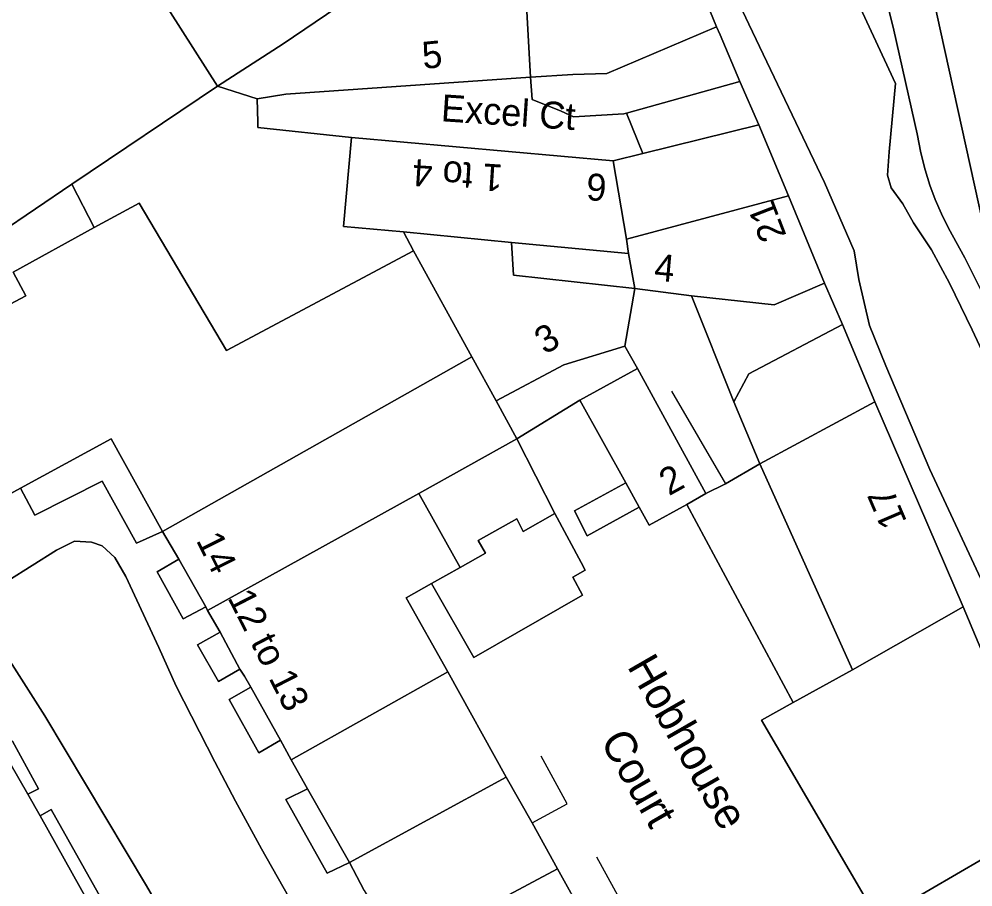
# Model space of a CAD drawing. Extents: x 529240 to 530363, y 179600 to 180767.
# Drawn here: x 529795.1 to 529848.2, y 180519 to 180567.3 of the extents above; entities that cross this region are included whole.
import ezdxf

# ---------------------------------------------------------------- set-up
doc = ezdxf.new("R2010")
doc.units = 0
for name, color, linetype in [('Building', 7, 'Continuous'), ('General surface', 7, 'Continuous'), ('Road Or Track', 7, 'Continuous'), ('Roadside', 7, 'Continuous'), ('Unclassified', 7, 'Continuous')]:
    doc.layers.add(name, color=color, linetype=linetype)

msp = doc.modelspace()

# ---------------------------------------------------------------- linework, layer by layer
at = {"layer": 'Building'}
for points in [[(529855.95, 180595.65), (529833.9, 180581.35), (529837.65, 180573.95), (529841.7, 180575.05), (529843.75, 180566.65), (529845.05, 180560.9), (529845.25, 180559.85), (529845.5, 180558.9), (529845.75, 180558.05), (529846.05, 180557.25), (529846.4, 180556.45), (529846.8, 180555.65), (529847.7, 180554), (529850.25, 180548.9)], [(529849.65, 180551.65), (529844.25, 180576.15), (529842, 180575.7), (529841.8, 180576.65), (529840.55, 180576.35), (529838.3, 180580.5), (529851.8, 180589.75)], [(529849.65, 180551.65), (529844.25, 180576.15), (529842, 180575.7), (529841.8, 180576.65), (529840.55, 180576.35), (529838.3, 180580.5), (529851.8, 180589.75), (529852.15, 180588.15), (529860.1, 180589.65)], [(529850.25, 180548.9), (529847.7, 180554), (529846.8, 180555.65), (529846.4, 180556.45), (529846.05, 180557.25), (529845.75, 180558.05), (529845.5, 180558.9), (529845.25, 180559.85), (529845.05, 180560.9), (529843.75, 180566.65), (529841.7, 180575.05), (529837.65, 180573.95), (529833.9, 180581.35)], [(529799.55, 180573.9), (529806.15, 180563.55)], [(529832.1, 180571.3), (529832.25, 180570.9), (529833.9, 180566.85)], [(529809.8, 180565.9), (529814, 180568.75)], [(529823.35, 180567.7), (529823.55, 180564.05)], [(529823.55, 180564.05), (529825.9, 180564.2), (529827.8, 180564.25), (529833.9, 180566.85)], [(529833.9, 180566.85), (529834.1, 180566.4), (529835.2, 180563.8)], [(529806.15, 180563.55), (529809.8, 180565.9)], [(529809.95, 180563.1), (529812.62, 180563.29), (529823.55, 180564.05)], [(529823.55, 180564.05), (529823.65, 180562.8), (529825.25, 180562.15), (529825.95, 180561.85), (529828.75, 180562), (529828.9, 180562.05)], [(529798.05, 180558.1), (529806.15, 180563.55)], [(529806.15, 180563.55), (529808.35, 180562.85)], [(529828.9, 180562.05), (529835.2, 180563.8)], [(529835.2, 180563.8), (529836.25, 180561.4)], [(529808.35, 180562.85), (529809.95, 180563.1)], [(529828.9, 180562.05), (529829.8, 180559.8)], [(529829.8, 180559.8), (529836.25, 180561.4)], [(529836.25, 180561.4), (529837.9, 180557.45)], [(529813.6, 180560.7), (529813.15, 180555.75), (529816.5, 180555.45)], [(529813.6, 180560.7), (529828.15, 180559.4)], [(529828.15, 180559.4), (529829.8, 180559.8)], [(529828.9, 180555.05), (529828.15, 180559.4)], [(529790.85, 180552.7), (529791, 180552.45), (529794.3, 180554.9), (529794, 180555.35), (529798.05, 180558.1)], [(529828.9, 180555.05), (529837.9, 180557.45)], [(529837.9, 180557.45), (529839.9, 180552.6)], [(529793, 180540), (529795.2, 180541.2), (529800.25, 180543.95), (529803.1, 180538.8), (529820.3, 180548.5), (529817.05, 180554.4), (529806.65, 180548.85), (529801.8, 180557.05), (529799.3, 180555.7), (529794.8, 180553.2), (529795.5, 180551.9), (529788.45, 180548.15)], [(529799.3, 180555.7), (529801.8, 180557.05), (529806.65, 180548.85), (529817.05, 180554.4)], [(529786.1, 180549.05), (529787.55, 180549.65), (529788.45, 180548.15), (529795.5, 180551.9), (529794.8, 180553.2), (529799.3, 180555.7)], [(529816.5, 180555.45), (529822.5, 180554.85)], [(529816.5, 180555.45), (529817.05, 180554.4)], [(529829, 180554.25), (529828.9, 180555.05)], [(529822.5, 180554.85), (529829, 180554.25)], [(529822.5, 180554.85), (529822.6, 180553.05), (529829.35, 180552.3)], [(529817.05, 180554.4), (529820.3, 180548.5)], [(529829.35, 180552.3), (529829, 180554.25)], [(529828.8, 180549.1), (529829.35, 180552.3)], [(529829.35, 180552.3), (529832.5, 180551.9)], [(529832.5, 180551.9), (529837.1, 180551.4), (529839.9, 180552.6)], [(529839.9, 180552.6), (529840.9, 180550.3)], [(529832.5, 180551.9), (529834.85, 180546)], [(529840.9, 180550.3), (529835.7, 180547.55), (529834.85, 180546)], [(529840.9, 180550.3), (529842.7, 180546)], [(529821.65, 180546.05), (529825.4, 180548.05), (529828.8, 180549.1)], [(529829.5, 180547.85), (529828.8, 180549.1)], [(529803.1, 180538.8), (529820.3, 180548.5)], [(529820.3, 180548.5), (529821.65, 180546.05)], [(529829.5, 180547.85), (529826.3, 180546.1)], [(529833.3, 180540.9), (529829.5, 180547.85)], [(529821.65, 180546.05), (529822.8, 180543.95)], [(529822.8, 180543.95), (529826.3, 180546.1)], [(529826.3, 180546.1), (529828.85, 180541.5)], [(529834.85, 180546), (529836.3, 180542.55)], [(529836.3, 180542.55), (529842.7, 180546)], [(529842.7, 180546), (529847.6, 180534.6)], [(529795.2, 180541.2), (529800.25, 180543.95), (529803.1, 180538.8)], [(529822.8, 180543.95), (529817.35, 180540.9)], [(529836.3, 180542.55), (529834.4, 180541.45)], [(529836.3, 180542.55), (529841.45, 180531.1)], [(529793, 180540), (529795.2, 180541.2)], [(529828.85, 180541.5), (529829.6, 180540.15)], [(529834.4, 180541.45), (529833.3, 180540.9)], [(529817.35, 180540.9), (529805.6, 180534.4)], [(529817.35, 180540.9), (529819.65, 180536.8)], [(529832.25, 180540.3), (529833.3, 180540.9)], [(529829.6, 180540.15), (529830.15, 180539.15), (529832.25, 180540.3)], [(529832.25, 180540.3), (529838.15, 180529.3)], [(529824.9, 180539.8), (529826.37, 180537.08), (529826.6, 180536.65), (529825.9, 180536.25), (529826.45, 180535.25), (529820.4, 180531.8), (529818.05, 180535.9)], [(529819.65, 180536.8), (529821.05, 180537.6), (529820.65, 180538.3), (529822.8, 180539.5), (529823.15, 180538.8), (529824.9, 180539.8)], [(529803.1, 180538.8), (529804, 180537.25)], [(529804, 180537.25), (529805.5, 180534.6)], [(529818.05, 180535.9), (529819.65, 180536.8)], [(529816.65, 180535.1), (529818.05, 180535.9)], [(529816.65, 180535.1), (529818.95, 180531)], [(529805.5, 180534.6), (529805.6, 180534.4)], [(529805.6, 180534.4), (529806.3, 180533.2)], [(529847.6, 180534.6), (529841.45, 180531.1)], [(529847.6, 180534.6), (529852.55, 180522.85), (529848.7, 180520.6)], [(529806.3, 180533.2), (529807.4, 180531.15)], [(529807.4, 180531.15), (529807.65, 180530.75), (529808, 180530.15)], [(529841.45, 180531.1), (529838.15, 180529.3)], [(529810.25, 180526.1), (529818.95, 180531)], [(529818.95, 180531), (529822.2, 180525.15)], [(529808, 180530.15), (529809.65, 180527.2)], [(529838.15, 180529.3), (529836.4, 180528.3), (529842.1, 180518.55)], [(529809.65, 180527.2), (529810.25, 180526.1)], [(529795.6, 180524.2), (529794.1, 180526.8)], [(529810.25, 180526.1), (529811.15, 180524.5)], [(529822.2, 180525.15), (529813.5, 180520.4)], [(529822.2, 180525.15), (529823.65, 180522.6)], [(529796.3, 180523), (529795.6, 180524.2)], [(529811.15, 180524.5), (529813.5, 180520.4)], [(529801.1, 180514.4), (529796.3, 180523)], [(529823.65, 180522.6), (529825.05, 180520.05)], [(529848.7, 180520.6), (529842.85, 180517.2)], [(529813.5, 180520.4), (529814.3, 180518.85)], [(529825.05, 180520.05), (529816.35, 180515.4)], [(529825.05, 180520.05), (529826.55, 180517.35)]]:
    msp.add_lwpolyline(points, dxfattribs=at)
for points in [[(529860.1, 180589.65), (529852.15, 180588.15), (529851.8, 180589.75), (529838.3, 180580.5), (529840.55, 180576.35), (529841.8, 180576.65), (529842, 180575.7), (529844.25, 180576.15), (529849.65, 180551.65), (529857.95, 180553.2), (529857.2, 180556.65), (529859.1, 180557.1), (529862.7, 180540.75), (529880.3, 180546.95), (529872.25, 180583.85), (529871.15, 180583.6), (529861.7, 180581.55)], [(529820.3, 180578.05), (529818.85, 180580.3), (529816, 180584.85), (529806, 180578.15), (529800.85, 180574.8), (529799.55, 180573.9), (529806.15, 180563.55), (529809.8, 180565.9), (529814, 180568.75), (529814.85, 180569.3), (529822, 180575.15)], [(529806.15, 180563.55), (529799.55, 180573.9), (529783.75, 180563.25), (529790.85, 180552.7), (529791, 180552.45), (529794.3, 180554.9), (529794, 180555.35), (529798.05, 180558.1)], [(529832.1, 180571.3), (529823.35, 180567.7), (529823.55, 180564.05), (529825.9, 180564.2), (529827.8, 180564.25), (529833.9, 180566.85), (529832.25, 180570.9)], [(529809.95, 180563.1), (529812.62, 180563.29), (529823.55, 180564.05), (529823.35, 180567.7), (529823.25, 180569.35), (529817.7, 180568.85), (529814, 180568.75), (529809.8, 180565.9), (529806.15, 180563.55), (529808.35, 180562.85)], [(529828.9, 180562.05), (529835.2, 180563.8), (529834.1, 180566.4), (529833.9, 180566.85), (529827.8, 180564.25), (529825.9, 180564.2), (529823.55, 180564.05), (529823.65, 180562.8), (529825.25, 180562.15), (529825.95, 180561.85), (529828.75, 180562)], [(529835.2, 180563.8), (529828.9, 180562.05), (529829.8, 180559.8), (529836.25, 180561.4)], [(529828.9, 180555.05), (529837.9, 180557.45), (529836.25, 180561.4), (529829.8, 180559.8), (529828.15, 180559.4)], [(529829, 180554.25), (529828.9, 180555.05), (529828.15, 180559.4), (529813.6, 180560.7), (529813.15, 180555.75), (529816.5, 180555.45), (529822.5, 180554.85)], [(529828.9, 180555.05), (529829, 180554.25), (529829.35, 180552.3), (529832.5, 180551.9), (529837.1, 180551.4), (529839.9, 180552.6), (529837.9, 180557.45)], [(529816.5, 180555.45), (529817.05, 180554.4), (529820.3, 180548.5), (529821.65, 180546.05), (529825.4, 180548.05), (529828.8, 180549.1), (529829.35, 180552.3), (529822.6, 180553.05), (529822.5, 180554.85)], [(529839.9, 180552.6), (529837.1, 180551.4), (529832.5, 180551.9), (529834.85, 180546), (529835.7, 180547.55), (529840.9, 180550.3)], [(529836.3, 180542.55), (529842.7, 180546), (529840.9, 180550.3), (529835.7, 180547.55), (529834.85, 180546)], [(529829.5, 180547.85), (529828.8, 180549.1), (529825.4, 180548.05), (529821.65, 180546.05), (529822.8, 180543.95), (529826.3, 180546.1)], [(529804, 180537.25), (529805.5, 180534.6), (529805.6, 180534.4), (529817.35, 180540.9), (529822.8, 180543.95), (529821.65, 180546.05), (529820.3, 180548.5), (529803.1, 180538.8)], [(529829.6, 180540.15), (529830.15, 180539.15), (529832.25, 180540.3), (529833.3, 180540.9), (529829.5, 180547.85), (529826.3, 180546.1), (529828.85, 180541.5)], [(529847.6, 180534.6), (529842.7, 180546), (529836.3, 180542.55), (529841.45, 180531.1)], [(529833.3, 180540.9), (529832.25, 180540.3), (529838.15, 180529.3), (529841.45, 180531.1), (529836.3, 180542.55), (529834.4, 180541.45)], [(529806.3, 180533.2), (529807.4, 180531.15), (529807.65, 180530.75), (529808, 180530.15), (529809.65, 180527.2), (529810.25, 180526.1), (529818.95, 180531), (529816.65, 180535.1), (529818.05, 180535.9), (529819.65, 180536.8), (529817.35, 180540.9), (529805.6, 180534.4)], [(529818.05, 180535.9), (529820.4, 180531.8), (529826.45, 180535.25), (529825.9, 180536.25), (529826.6, 180536.65), (529826.37, 180537.08), (529824.9, 180539.8), (529823.15, 180538.8), (529822.8, 180539.5), (529820.65, 180538.3), (529821.05, 180537.6), (529819.65, 180536.8)], [(529841.45, 180531.1), (529838.15, 180529.3), (529836.4, 180528.3), (529842.1, 180518.55), (529842.85, 180517.2), (529848.7, 180520.6), (529852.55, 180522.85), (529847.6, 180534.6)], [(529768.1, 180490.9), (529784.4, 180500), (529791, 180503.75), (529802.3, 180510.1), (529803.2, 180510.75), (529801.1, 180514.4), (529796.3, 180523), (529795.6, 180524.2), (529794.1, 180526.8), (529793.35, 180528.15), (529791.95, 180530.55), (529791.05, 180532.2), (529775.65, 180523.35), (529778.6, 180518.05), (529771.5, 180513.85), (529769.5, 180512.7), (529759.2, 180506.6), (529760.3, 180504.8), (529760.85, 180503.85), (529761.8, 180504.3), (529764.3, 180500), (529767.75, 180494.05), (529766.65, 180493.35), (529766.95, 180492.85)], [(529813.5, 180520.4), (529822.2, 180525.15), (529818.95, 180531), (529810.25, 180526.1), (529811.15, 180524.5)], [(529816.35, 180515.4), (529825.05, 180520.05), (529823.65, 180522.6), (529822.2, 180525.15), (529813.5, 180520.4), (529814.3, 180518.85)], [(529841.25, 180506.1), (529853, 180512.7), (529848.7, 180520.6), (529842.85, 180517.2), (529836.9, 180513.75)], [(529823.3, 180512.15), (529828, 180514.75), (529826.55, 180517.35), (529825.05, 180520.05), (529816.35, 180515.4), (529817.1, 180513.9), (529819.35, 180509.95)]]:
    msp.add_lwpolyline(points, close=True, dxfattribs=at)
at = {"layer": 'General surface'}
for points in [[(529808.35, 180562.85), (529808.39, 180561.55), (529808.4, 180561.25), (529813.6, 180560.7), (529828.15, 180559.4), (529829.8, 180559.8), (529828.9, 180562.05), (529828.75, 180562), (529825.95, 180561.85), (529825.25, 180562.15), (529823.65, 180562.8), (529823.55, 180564.05), (529812.62, 180563.29), (529809.95, 180563.1)], [(529798.05, 180558.1), (529799.3, 180555.7), (529801.8, 180557.05), (529806.65, 180548.85), (529817.05, 180554.4), (529816.5, 180555.45), (529813.15, 180555.75), (529813.6, 180560.7), (529808.4, 180561.25), (529808.39, 180561.55), (529808.35, 180562.85), (529806.15, 180563.55)], [(529798.05, 180558.1), (529794, 180555.35), (529794.3, 180554.9), (529791, 180552.45), (529790.85, 180552.7), (529785.9, 180549.35), (529786.1, 180549.05), (529787.55, 180549.65), (529788.45, 180548.15), (529795.5, 180551.9), (529794.8, 180553.2), (529799.3, 180555.7)], [(529822.5, 180554.85), (529822.6, 180553.05), (529829.35, 180552.3), (529829, 180554.25)], [(529834.4, 180541.45), (529836.3, 180542.55), (529834.85, 180546), (529832.5, 180551.9), (529829.35, 180552.3), (529828.8, 180549.1), (529829.5, 180547.85), (529833.3, 180540.9)], [(529803.1, 180538.8), (529800.25, 180543.95), (529795.2, 180541.2), (529796, 180539.7), (529799.75, 180541.6), (529801.65, 180538.15)], [(529819.65, 180536.8), (529821.05, 180537.6), (529820.65, 180538.3), (529822.8, 180539.5), (529823.15, 180538.8), (529824.9, 180539.8), (529822.8, 180543.95), (529817.35, 180540.9)], [(529829.6, 180540.15), (529828.85, 180541.5), (529826, 180539.95), (529826.7, 180538.55)], [(529804, 180537.25), (529802.8, 180536.55), (529804.25, 180533.95), (529805.5, 180534.6)], [(529806.3, 180533.2), (529805.05, 180532.5), (529806.2, 180530.45), (529807.4, 180531.15)], [(529808, 180530.15), (529806.8, 180529.45), (529808.45, 180526.5), (529809.65, 180527.2)], [(529795.6, 180524.2), (529796.2, 180524.5), (529794.75, 180527.15), (529794.1, 180526.8)], [(529811.15, 180524.5), (529809.95, 180523.9), (529812.25, 180519.8), (529813.5, 180520.4)], [(529801.1, 180514.4), (529801.7, 180514.8), (529796.9, 180523.35), (529796.3, 180523)]]:
    msp.add_lwpolyline(points, close=True, dxfattribs=at)
msp.add_lwpolyline([(529842.1, 180518.55), (529836.4, 180528.3), (529838.15, 180529.3), (529832.25, 180540.3), (529830.15, 180539.15), (529829.6, 180540.15), (529826.7, 180538.55), (529826, 180539.95), (529828.85, 180541.5), (529826.3, 180546.1), (529822.8, 180543.95), (529824.9, 180539.8), (529826.37, 180537.08), (529826.6, 180536.65), (529825.9, 180536.25), (529826.45, 180535.25), (529820.4, 180531.8), (529818.05, 180535.9), (529816.65, 180535.1), (529818.95, 180531), (529822.2, 180525.15), (529823.65, 180522.6), (529825.05, 180520.05), (529826.55, 180517.35)], dxfattribs=at)
at = {"layer": 'Road Or Track'}
for points in [[(529822.76, 180590.88), (529824.3, 180590.75), (529831.5, 180575.85), (529835.7, 180567), (529839.9, 180558.2), (529841.55, 180554.4), (529841.8, 180552.8), (529842.4, 180550.25), (529843.3, 180548), (529845.75, 180542.25), (529849.1, 180535.05)], [(529831.5, 180575.85), (529835.7, 180567), (529839.9, 180558.2), (529841.55, 180554.4), (529841.8, 180552.8), (529842.4, 180550.25), (529843.3, 180548), (529845.75, 180542.25), (529849.1, 180535.05)], [(529854.8, 180537.25), (529854.4, 180537.5), (529853.6, 180538.75), (529852.75, 180540.65), (529851.8, 180542.5), (529850.6, 180544.9), (529849.35, 180547.35), (529848.1, 180550), (529846.85, 180552.6), (529845.85, 180554.45), (529844.85, 180555.95), (529844.25, 180557), (529843.6, 180557.9), (529843.4, 180558.6), (529843.5, 180559.9), (529843.85, 180563.7), (529840.55, 180570.8), (529838.95, 180572.05), (529836.5, 180573.5), (529835.85, 180574)], [(529849.35, 180547.35), (529848.1, 180550), (529846.85, 180552.6), (529845.85, 180554.45), (529844.85, 180555.95), (529844.25, 180557), (529843.6, 180557.9), (529843.4, 180558.6), (529843.5, 180559.9), (529843.85, 180563.7), (529840.55, 180570.8)], [(529810.1, 180518.5), (529808.6, 180521.15), (529807.15, 180523.8), (529806, 180526), (529803.85, 180530.2), (529802.9, 180532.35), (529801.05, 180536.3), (529800.45, 180537.35), (529799.75, 180538), (529799.15, 180538.2), (529798.2, 180538.25), (529797.2, 180537.75), (529794.5, 180536.05), (529793.5, 180535.15), (529793.35, 180533.9), (529793.75, 180532.85), (529794.6, 180531.6), (529796.55, 180528.55), (529802.2, 180519.1), (529813.25, 180500)], [(529813.25, 180500), (529802.2, 180519.1), (529796.55, 180528.55), (529794.6, 180531.6), (529793.75, 180532.85), (529793.35, 180533.9), (529793.5, 180535.15), (529794.5, 180536.05), (529797.2, 180537.75), (529798.2, 180538.25), (529799.15, 180538.2), (529799.75, 180538), (529800.45, 180537.35), (529801.05, 180536.3), (529802.9, 180532.35), (529803.85, 180530.2), (529806, 180526), (529807.15, 180523.8), (529808.6, 180521.15), (529810.1, 180518.5)]]:
    msp.add_lwpolyline(points, dxfattribs=at)
at = {"layer": 'Roadside'}
for points in [[(529850.25, 180548.9), (529847.7, 180554), (529846.8, 180555.65), (529846.4, 180556.45), (529846.05, 180557.25), (529845.75, 180558.05), (529845.5, 180558.9), (529845.25, 180559.85), (529845.05, 180560.9), (529843.75, 180566.65), (529841.7, 180575.05), (529837.65, 180573.95), (529833.9, 180581.35), (529831.1, 180586.7), (529828, 180592.7), (529828.05, 180593.2), (529828.25, 180593.5), (529828.7, 180593.7), (529829.5, 180594.05), (529844.4, 180597.85), (529866.75, 180603.55)], [(529849.1, 180535.05), (529845.75, 180542.25), (529843.3, 180548), (529842.4, 180550.25), (529841.8, 180552.8), (529841.55, 180554.4), (529839.9, 180558.2), (529835.7, 180567), (529831.5, 180575.85), (529824.3, 180590.75), (529822.76, 180590.88), (529822.55, 180590.9), (529819.5, 180588.94), (529818.5, 180588.3), (529813.95, 180585.2), (529805.2, 180579.55), (529803.4, 180577.9), (529792.5, 180570.35)], [(529783.75, 180563.25), (529799.55, 180573.9), (529800.85, 180574.8), (529806, 180578.15), (529816, 180584.85), (529821.75, 180588.7), (529823.65, 180588.05), (529825.35, 180584.85), (529828.05, 180579.85), (529830.3, 180575.15), (529832.1, 180571.3), (529832.25, 180570.9), (529833.9, 180566.85), (529834.1, 180566.4), (529835.2, 180563.8), (529836.25, 180561.4), (529837.9, 180557.45), (529839.9, 180552.6), (529840.9, 180550.3), (529842.7, 180546), (529847.6, 180534.6), (529852.55, 180522.85), (529848.7, 180520.6), (529853, 180512.7)], [(529840.55, 180570.8), (529843.85, 180563.7), (529843.5, 180559.9), (529843.4, 180558.6), (529843.6, 180557.9), (529844.25, 180557), (529844.85, 180555.95), (529845.85, 180554.45), (529846.85, 180552.6), (529848.1, 180550), (529849.35, 180547.35)], [(529814.3, 180518.85), (529813.5, 180520.4), (529812.25, 180519.8), (529809.95, 180523.9), (529811.15, 180524.5), (529810.25, 180526.1), (529809.65, 180527.2), (529808.45, 180526.5), (529806.8, 180529.45), (529808, 180530.15), (529807.65, 180530.75), (529807.4, 180531.15), (529806.2, 180530.45), (529805.05, 180532.5), (529806.3, 180533.2), (529805.6, 180534.4), (529805.5, 180534.6), (529804.25, 180533.95), (529802.8, 180536.55), (529804, 180537.25), (529803.1, 180538.8), (529801.65, 180538.15), (529799.75, 180541.6), (529796, 180539.7), (529795.2, 180541.2), (529793, 180540)], [(529813.25, 180500), (529802.2, 180519.1), (529796.55, 180528.55), (529794.6, 180531.6), (529793.75, 180532.85), (529793.35, 180533.9), (529793.5, 180535.15), (529794.5, 180536.05), (529797.2, 180537.75), (529798.2, 180538.25), (529799.15, 180538.2), (529799.75, 180538), (529800.45, 180537.35), (529801.05, 180536.3), (529802.9, 180532.35), (529803.85, 180530.2), (529806, 180526), (529807.15, 180523.8), (529808.6, 180521.15), (529810.1, 180518.5)], [(529794.75, 180527.15), (529796.2, 180524.5), (529795.6, 180524.2), (529796.3, 180523), (529796.9, 180523.35), (529801.7, 180514.8)]]:
    msp.add_lwpolyline(points, dxfattribs=at)
at = {"layer": 'Unclassified'}
for points in [[(529808.35, 180562.85), (529808.39, 180561.55), (529808.4, 180561.25), (529813.6, 180560.7)], [(529798.05, 180558.1), (529799.3, 180555.7)], [(529831.4, 180546.6), (529834.4, 180541.45)], [(529822.8, 180543.95), (529824.9, 180539.8)], [(529795.2, 180541.2), (529796, 180539.7), (529799.75, 180541.6), (529801.65, 180538.15), (529803.1, 180538.8)], [(529828.85, 180541.5), (529826, 180539.95), (529826.7, 180538.55), (529829.6, 180540.15)], [(529804, 180537.25), (529802.8, 180536.55), (529804.25, 180533.95), (529805.5, 180534.6)], [(529806.3, 180533.2), (529805.05, 180532.5), (529806.2, 180530.45), (529807.4, 180531.15)], [(529808, 180530.15), (529806.8, 180529.45), (529808.45, 180526.5), (529809.65, 180527.2)], [(529795.6, 180524.2), (529796.2, 180524.5), (529794.75, 180527.15), (529794.1, 180526.8)], [(529823.65, 180522.6), (529825.6, 180523.65), (529824.15, 180526.3)], [(529811.15, 180524.5), (529809.95, 180523.9), (529812.25, 180519.8), (529813.5, 180520.4)], [(529801.1, 180514.4), (529801.7, 180514.8), (529796.9, 180523.35), (529796.3, 180523)], [(529826.55, 180517.35), (529828.5, 180518.4), (529827.25, 180520.7)]]:
    msp.add_lwpolyline(points, dxfattribs=at)

# ---------------------------------------------------------------- texts
for s, height, rotation, p in [('5', 1.5, 5.7, (529817.6, 180564.5)), ('Excel Ct', 1.5, 356.2, (529818.55, 180561.6)), ('1 to 4', 1.5, 176.3, (529822.05, 180559.18)), ('6', 1.5, 176.3, (529827.83, 180558.64)), ('21', 1.5, 111.1, (529837.8, 180555.25)), ('4', 1.5, 354.9, (529830.39, 180552.75)), ('3', 1.5, 30.3, (529824.35, 180548.6)), ('2', 1.5, 29, (529831.25, 180540.75)), ('17', 1.5, 113.2, (529844.5, 180539.35)), ('14', 1.5, 296.5, (529804.94, 180538.31)), ('12 to 13', 1.5, 297.1, (529806.69, 180535.12)), ('Hobhouse', 1.75, 299.9, (529828.9, 180531.3)), ('Court', 1.75, 299.9, (529827.4, 180527.15))]:
    msp.add_text(s, height=height, rotation=rotation, dxfattribs=at).set_placement(p)

doc.saveas('drawing.dxf')
